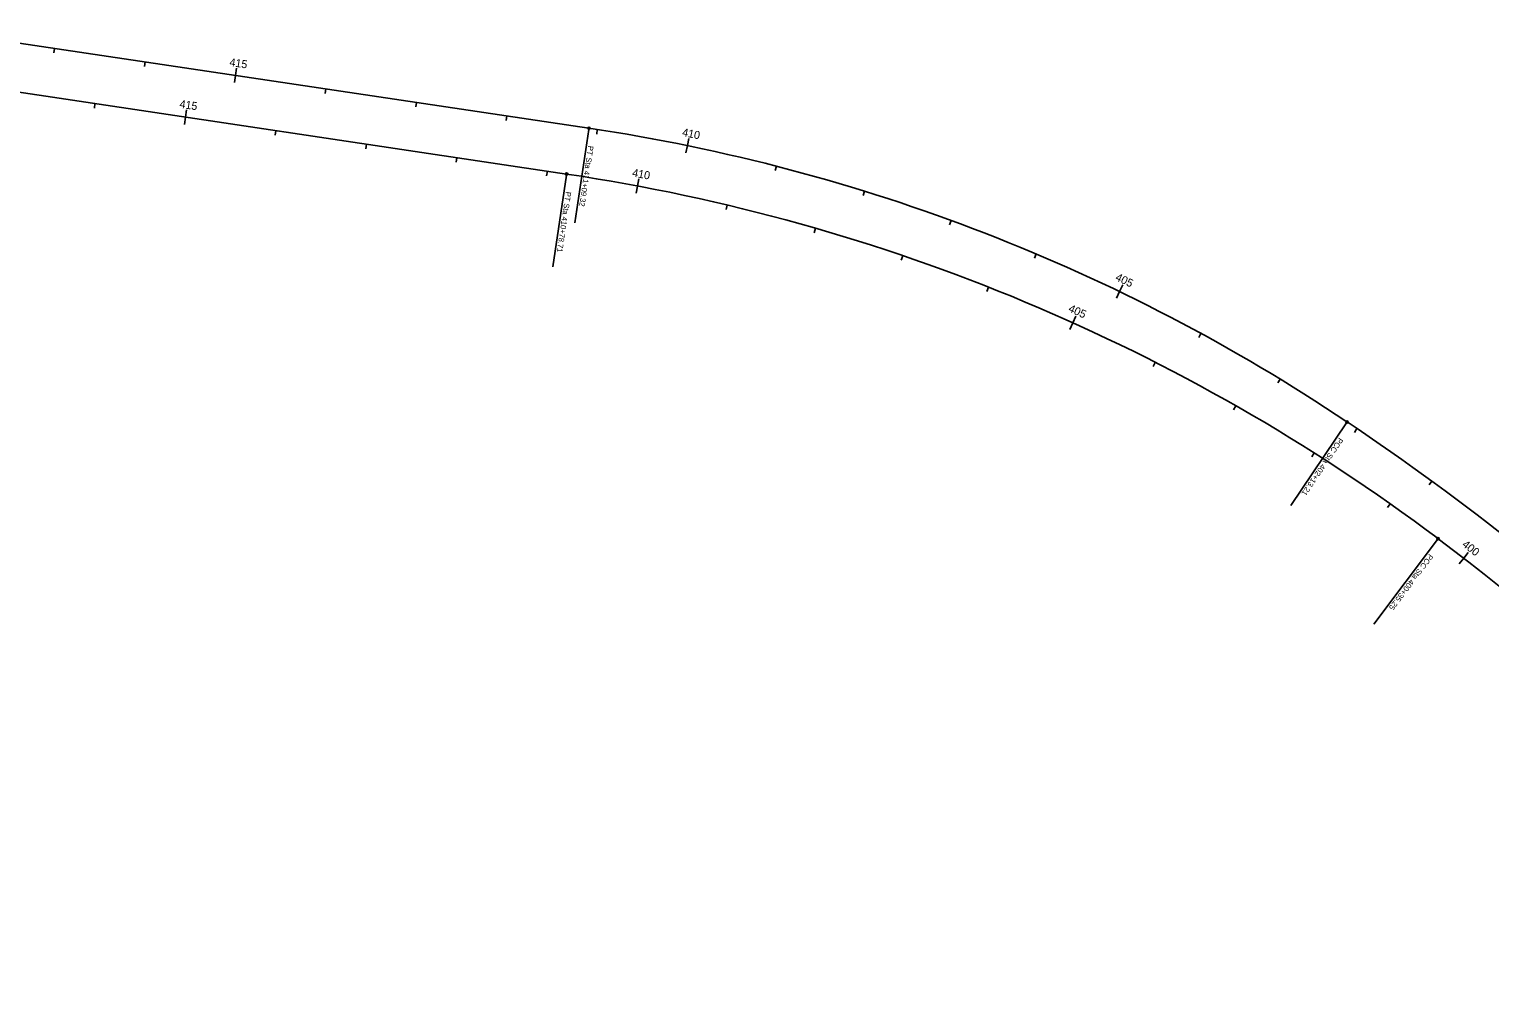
# Model space of a CAD drawing. Extents: x 1602163 to 1612907, y 1087635 to 1096265.
# Drawn here: x 1609104 to 1610701, y 1093472 to 1094534 of the extents above; entities that cross this region are included whole.
import ezdxf

# ---------------------------------------------------------------- set-up
doc = ezdxf.new("R2010")
doc.units = 0
for name, color, linetype in [('RD_HC_Cl', 7, 'Continuous'), ('RD_HC_Data_Tic', 7, 'Continuous'), ('RD_HC_Points', 7, 'Continuous'), ('RD_HC_TX_Sta50', 7, 'Continuous')]:
    doc.layers.add(name, color=color, linetype=linetype)

msp = doc.modelspace()

# ---------------------------------------------------------------- linework, layer by layer
at = {"layer": 'RD_HC_Cl'}
for p, q in [((1609716.2, 1094425.3), (1608991.5, 1094533.5)), ((1609691.8, 1094375.1), (1608983.5, 1094480.9))]:
    msp.add_line(p, q, dxfattribs=at)
for centre, radius, start, end in [((1609417.4, 1092424.2), 2023.2, 56.1301, 81.5065), ((1609381.3, 1092295.5), 2102.7, 53.0731, 81.5065), ((1608910.9, 1091669.6), 2932.1, 37.9336, 56.1301), ((1608910.9, 1091669.6), 2885.6, 39.6334, 53.0731)]:
    msp.add_arc(centre, radius, start, end, dxfattribs=at)
at = {"layer": 'RD_HC_Data_Tic'}
for p, q in [((1609132, 1094512.5), (1609131.3, 1094507.6)), ((1609230.9, 1094497.7), (1609230.2, 1094492.8)), ((1609329.8, 1094483), (1609328.6, 1094475.1)), ((1609329.8, 1094483), (1609331, 1094490.9)), ((1609428.7, 1094468.2), (1609428, 1094463.3)), ((1609176.2, 1094452.1), (1609175.5, 1094447.1)), ((1609527.6, 1094453.4), (1609526.9, 1094448.5)), ((1609275.1, 1094437.3), (1609274, 1094429.4)), ((1609275.1, 1094437.3), (1609276.3, 1094445.2)), ((1609626.5, 1094438.7), (1609625.8, 1094433.7)), ((1609374, 1094422.5), (1609373.3, 1094417.6)), ((1609725.4, 1094423.9), (1609724.7, 1094418.9)), ((1609473, 1094407.8), (1609472.2, 1094402.8)), ((1609823.8, 1094406.2), (1609822.2, 1094398.4)), ((1609823.8, 1094406.2), (1609825.4, 1094414.1)), ((1609571.9, 1094393), (1609571.1, 1094388)), ((1609921.3, 1094383.7), (1609920, 1094378.9)), ((1609670.8, 1094378.2), (1609670, 1094373.3)), ((1609769.4, 1094362), (1609770.9, 1094369.9)), ((1609769.4, 1094362), (1609767.9, 1094354.1)), ((1610017.5, 1094356.4), (1610016, 1094351.7)), ((1609867.2, 1094341.2), (1609866.1, 1094336.3)), ((1610112.2, 1094324.4), (1610110.5, 1094319.7)), ((1609963.9, 1094315.8), (1609962.6, 1094311)), ((1610205.2, 1094287.8), (1610203.3, 1094283.2)), ((1610059.3, 1094285.8), (1610057.7, 1094281.1)), ((1610153.2, 1094251.3), (1610151.3, 1094246.7)), ((1610296.3, 1094246.6), (1610292.9, 1094239.4)), ((1610296.3, 1094246.6), (1610299.8, 1094253.8)), ((1610245.3, 1094212.4), (1610242, 1094205.1)), ((1610245.3, 1094212.4), (1610248.6, 1094219.7)), ((1610385.3, 1094200.9), (1610382.9, 1094196.5)), ((1610335.4, 1094169.2), (1610333.2, 1094164.7)), ((1610471.9, 1094150.9), (1610469.3, 1094146.7)), ((1610423.4, 1094121.7), (1610421, 1094117.3)), ((1610555.9, 1094096.7), (1610553.1, 1094092.6)), ((1610509.1, 1094070.1), (1610506.4, 1094065.9)), ((1610637.7, 1094039.2), (1610634.8, 1094035.2)), ((1610592.2, 1094014.4), (1610589.3, 1094010.4)), ((1610672.6, 1093955), (1610667.7, 1093948.7)), ((1610672.6, 1093955), (1610677.5, 1093961.3))]:
    msp.add_line(p, q, dxfattribs=at)
at = {"layer": 'RD_HC_Points'}
for p, q in [((1609716, 1094424), (1609700.8, 1094321.8)), ((1609691.6, 1094373.8), (1609676.7, 1094273.6)), ((1610544.3, 1094103.1), (1610483.4, 1094012.5)), ((1610643.8, 1093975.3), (1610574.2, 1093882.8))]:
    msp.add_line(p, q, dxfattribs=at)
for centre in [(1609716.2, 1094425.3), (1609691.8, 1094375.1), (1610545, 1094104.1), (1610644.5, 1093976.3)]:
    msp.add_circle(centre, 1.25, dxfattribs=at)

# ---------------------------------------------------------------- texts
for s, rotation, p in [('PT Sta 411+09.32', 261.5065, (1609715.4, 1094406.4)), ('PT Sta 410+78.71', 261.5065, (1609691, 1094356.2)), ('PCC Sta 402+13.21', 236.1301, (1610536.2, 1094087.4)), ('PCC Sta 400+35.25', 233.0731, (1610634.9, 1093960.2))]:
    msp.add_text(s, height=6, rotation=rotation, dxfattribs=at).set_placement(p)
at = {"layer": 'RD_HC_TX_Sta50'}
for s, rotation, p in [('415', 351.5065, (1609322.8, 1094493.4)), ('415', 351.5065, (1609268.2, 1094447.7)), ('410', 348.4109, (1609817.6, 1094416.9)), ('410', 349.3617, (1609763, 1094372.6)), ('405', 334.2515, (1610291, 1094259.4)), ('405', 335.7372, (1610239.6, 1094225.1)), ('400', 322.3732, (1610670.1, 1093968.6))]:
    msp.add_text(s, height=8.75, rotation=rotation, dxfattribs=at).set_placement(p)

doc.saveas('drawing.dxf')
